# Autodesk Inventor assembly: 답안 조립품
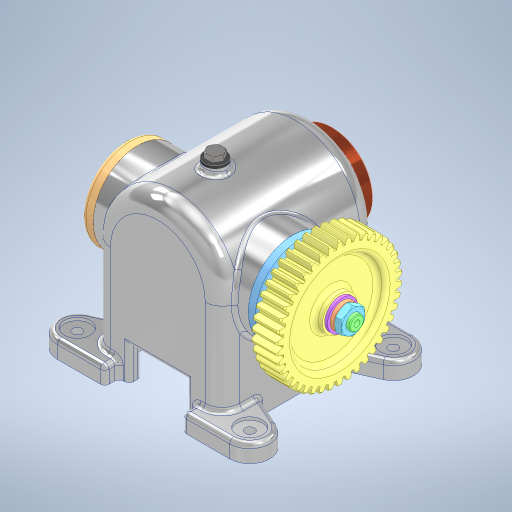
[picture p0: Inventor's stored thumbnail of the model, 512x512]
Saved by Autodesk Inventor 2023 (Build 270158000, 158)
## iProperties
Created: 2024-09
Part Number: 답안 조립품
Document SubType Name: Assembly
Designer: home
Author: home
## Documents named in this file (17)
- C:\Users\home\Desktop\740904V1025\답안 조립품.iam
- C:\Users\home\Desktop\740904V1025\본체.ipt
- C:\Users\home\Documents\Inventor\깊은 홈 볼베어링 6203.ipt
- C:\Users\home\Desktop\740904V1025\가져온 구성요소\뒷커버\뒷커버.ipt
- C:\Users\home\Desktop\740904V1025\가져온 구성요소\로드\로드.ipt
- C:\Users\home\Desktop\740904V1025\가져온 구성요소\부시\부시.ipt
- C:\Users\home\Desktop\740904V1025\가져온 구성요소\스퍼 기어\스퍼 기어.ipt
- C:\Users\home\Desktop\740904V1025\가져온 구성요소\스프링와셔 M10\스프링와셔 M10.ipt
- C:\Users\home\Desktop\740904V1025\가져온 구성요소\실링 패드\실링 패드.ipt
- C:\Users\home\Desktop\740904V1025\가져온 구성요소\앞커버\앞커버.ipt
- C:\Users\home\Desktop\740904V1025\가져온 구성요소\오일실 17 32 8\오일실 17 32 8.ipt
- C:\Users\home\Desktop\740904V1025\가져온 구성요소\육각 너트 M10x1\육각 너트 M10x1.ipt
- C:\Users\home\Desktop\740904V1025\가져온 구성요소\육각 머리 볼트 M6x0.75x12\육각 머리 볼트 M6x0.75x12.ipt
- C:\Users\home\Desktop\740904V1025\가져온 구성요소\육각 소켓 머리 볼트 M4x10\육각 소켓 머리 볼트 M4x10.ipt
- C:\Users\home\Desktop\740904V1025\가져온 구성요소\편심축\편심축.ipt
- C:\Users\home\Desktop\740904V1025\가져온 구성요소\평와셔 M10\평와셔 M10.ipt
- C:\Users\home\Desktop\740904V1025\가져온 구성요소\평행키 3x3x14\평행키 3x3x14.ipt
